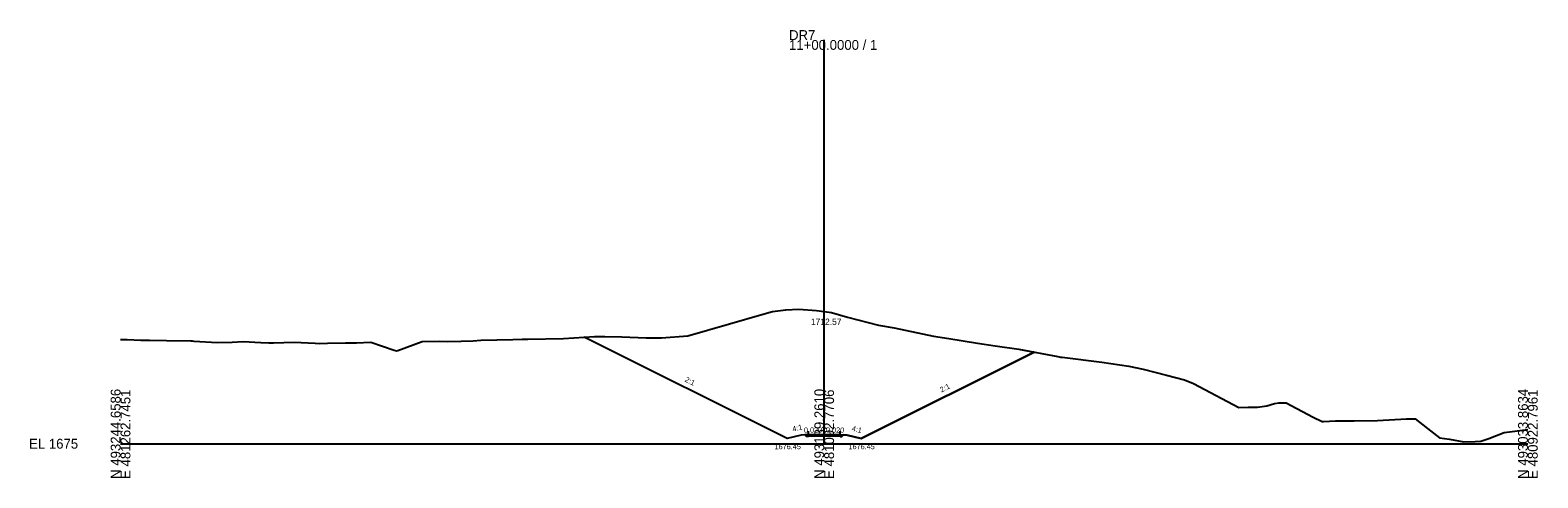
# Model space of a CAD drawing. Extents: x -26 to 403, y -10 to 4215.
# Drawn here: x -25.7 to 402.8, y 990.3 to 1117.5 of the extents above; entities that cross this region are included whole.
import ezdxf

# ---------------------------------------------------------------- set-up
doc = ezdxf.new("R2010")
doc.units = 0
for name, color, linetype in [('Exist Cross Section Cell', 7, 'Continuous'), ('Exist XS Center Line Elevation Label', 7, 'Continuous'), ('Exist XS Ground Line', 7, 'Continuous'), ('Prop XS Ditch Slope Text', 7, 'Continuous'), ('Prop XS Ditch Standard Text', 7, 'Continuous'), ('Prop XS Dump Level', 7, 'Continuous'), ('Prop XS Earthwork Shape', 7, 'Continuous'), ('Prop XS EOT Tick Mark', 7, 'Continuous'), ('Prop XS Finish Grade', 7, 'Continuous'), ('Prop XS Finish Grade Earthwork', 7, 'Continuous'), ('Prop XS Finish Grade Pavement', 7, 'Continuous'), ('Prop XS Hydro Typical Ditch Data', 7, 'Continuous'), ('Prop XS Pvmt Edge Slope', 7, 'Continuous'), ('Prop XS SE Text', 7, 'Continuous'), ('Prop XS Shoulder Borrow Shape', 7, 'Continuous'), ('Prop XS Side Slope Text', 7, 'Continuous'), ('Prop XS Subgrade Earthwork', 7, 'Continuous')]:
    doc.layers.add(name, color=color, linetype=linetype)

msp = doc.modelspace()

# ---------------------------------------------------------------- linework, layer by layer
at = {"layer": 'Exist Cross Section Cell'}
for p, q in [((200, 1000), (200, 1114.74)), ((0, 1000), (200, 1000)), ((200, 1000), (400, 1000))]:
    msp.add_line(p, q, dxfattribs=at)
at = {"layer": 'Exist XS Ground Line'}
msp.add_lwpolyline([(0, 1029.58), (1.89, 1029.58), (5.79, 1029.48), (8.21, 1029.43), (13.06, 1029.3), (19.98, 1029.23), (20.32, 1029.23), (20.86, 1029.19), (27.58, 1028.81), (31.75, 1028.9), (34.85, 1029.1), (39.84, 1028.79), (42.11, 1028.67), (43.52, 1028.72), (49.38, 1028.88), (55.29, 1028.57), (56.64, 1028.53), (58.82, 1028.59), (63.91, 1028.72), (67.06, 1028.7), (71.17, 1028.88), (77.8, 1026.57), (78.43, 1026.44), (78.83, 1026.48), (85.7, 1029.08), (90.59, 1029.13), (92.96, 1029.02), (96.78, 1029.18), (100.23, 1029.25), (102.36, 1029.42), (111.47, 1029.59), (114.13, 1029.69), (115.76, 1029.72), (125.9, 1029.94), (134.74, 1030.49), (137.67, 1030.47), (142.45, 1030.38), (149.44, 1030.06), (153.72, 1030.13), (161.21, 1030.71), (173.08, 1034.03), (182.29, 1036.73), (185.3, 1037.55), (189.12, 1038.09), (192.82, 1038.25), (197.83, 1037.89), (200, 1037.57), (202.1, 1037.26), (206.59, 1035.98), (215.42, 1033.74), (219.93, 1032.9), (231.09, 1030.53), (235.38, 1029.92), (243.59, 1028.6), (248.62, 1027.83), (255.36, 1026.85), (266.36, 1024.77), (267.13, 1024.64), (267.6, 1024.59), (278.89, 1023.14), (286.58, 1022.07), (290.66, 1021.2), (297.33, 1019.44), (302.43, 1018.14), (305.01, 1017.09), (317.87, 1010.31), (320.54, 1010.39), (323.12, 1010.36), (325.83, 1010.81), (327.98, 1011.39), (329.23, 1011.64), (331.3, 1011.66), (338.97, 1007.54), (341.53, 1006.3), (341.95, 1006.35), (345.35, 1006.51), (350.64, 1006.51), (357.22, 1006.6), (365.48, 1007.05), (368, 1007.1), (371.48, 1004.36), (374.9, 1001.72), (377.71, 1001.28), (381.84, 1000.55), (385.03, 1000.62), (386.63, 1000.74), (388.91, 1001.51), (393.28, 1003.15), (400, 1004.09)], dxfattribs=at)
at = {"layer": 'Prop XS Dump Level'}
for p, q in [((195.5, 1002.61), (200, 1002.7)), ((200, 1002.7), (204.5, 1002.61))]:
    msp.add_line(p, q, dxfattribs=at)
at = {"layer": 'Prop XS Earthwork Shape'}
msp.add_lwpolyline([(204.5, 1002.07), (200, 1002.16), (195.5, 1002.07), (194.95, 1002.05), (194.48, 1002.52), (193.5, 1002.45), (189.5, 1001.45), (131.78, 1030.3), (134.74, 1030.49), (137.67, 1030.47), (142.45, 1030.38), (149.44, 1030.06), (153.72, 1030.13), (161.21, 1030.71), (173.08, 1034.03), (182.29, 1036.73), (185.3, 1037.55), (189.12, 1038.09), (192.82, 1038.25), (197.83, 1037.89), (200, 1037.57), (202.1, 1037.26), (206.59, 1035.98), (215.42, 1033.74), (219.93, 1032.9), (231.09, 1030.53), (235.38, 1029.92), (243.59, 1028.6), (248.62, 1027.83), (255.36, 1026.85), (259.68, 1026.03), (210.5, 1001.45), (206.5, 1002.45), (205.52, 1002.52), (205.05, 1002.05)], close=True, dxfattribs=at)
at = {"layer": 'Prop XS EOT Tick Mark'}
for p, q in [((195.5, 1002.61), (195.5, 1003.61)), ((204.5, 1002.61), (204.5, 1003.61))]:
    msp.add_line(p, q, dxfattribs=at)
at = {"layer": 'Prop XS Finish Grade'}
for p, q in [((195.5, 1002.61), (194.48, 1002.52)), ((204.5, 1002.61), (205.52, 1002.52))]:
    msp.add_line(p, q, dxfattribs=at)
at = {"layer": 'Prop XS Finish Grade Earthwork'}
for p, q in [((189.5, 1001.45), (131.78, 1030.3)), ((210.5, 1001.45), (259.68, 1026.03)), ((193.5, 1002.45), (189.5, 1001.45)), ((194.48, 1002.52), (193.5, 1002.45)), ((205.52, 1002.52), (206.5, 1002.45)), ((206.5, 1002.45), (210.5, 1001.45))]:
    msp.add_line(p, q, dxfattribs=at)
at = {"layer": 'Prop XS Finish Grade Pavement'}
for p, q in [((195.5, 1002.61), (200, 1002.7)), ((200, 1002.7), (204.5, 1002.61))]:
    msp.add_line(p, q, dxfattribs=at)
at = {"layer": 'Prop XS Hydro Typical Ditch Data'}
for p, q in [((189.5, 1001.45), (131.78, 1030.3)), ((210.5, 1001.45), (259.68, 1026.03)), ((193.5, 1002.45), (189.5, 1001.45)), ((206.5, 1002.45), (210.5, 1001.45))]:
    msp.add_line(p, q, dxfattribs=at)
at = {"layer": 'Prop XS Pvmt Edge Slope'}
for p, q in [((195.5, 1002.61), (194.95, 1002.05)), ((204.5, 1002.61), (205.05, 1002.05))]:
    msp.add_line(p, q, dxfattribs=at)
at = {"layer": 'Prop XS Shoulder Borrow Shape'}
for points in [[(195.5, 1002.61), (194.48, 1002.52), (194.95, 1002.05)], [(195.5, 1002.61), (194.48, 1002.52), (194.95, 1002.05)], [(204.5, 1002.61), (205.52, 1002.52), (205.05, 1002.05)], [(204.5, 1002.61), (205.52, 1002.52), (205.05, 1002.05)]]:
    msp.add_lwpolyline(points, close=True, dxfattribs=at)
at = {"layer": 'Prop XS Subgrade Earthwork'}
for p, q in [((194.95, 1002.05), (194.48, 1002.52)), ((195.5, 1002.07), (194.95, 1002.05)), ((200, 1002.16), (195.5, 1002.07)), ((204.5, 1002.07), (200, 1002.16)), ((204.5, 1002.07), (205.05, 1002.05)), ((205.05, 1002.05), (205.52, 1002.52))]:
    msp.add_line(p, q, dxfattribs=at)

# ---------------------------------------------------------------- texts
at = {"layer": 'Exist Cross Section Cell'}
for s, p in [('11+00.0000 / 1', (190, 1111.94)), ('DR7', (190, 1114.74)), ('EL 1675', (-26, 998.6))]:
    msp.add_text(s, height=2.8, dxfattribs=at).set_placement(p)
for s, p in [('N 493244.6586', (0, 990)), ('E 481262.7451', (2.8, 990)), ('N 493139.2610', (200, 990)), ('E 481092.7706', (202.8, 990)), ('N 493033.8634', (400, 990)), ('E 480922.7961', (402.8, 990))]:
    msp.add_text(s, height=2.8, rotation=90, dxfattribs=at).set_placement(p)
at = {"layer": 'Exist XS Center Line Elevation Label'}
msp.add_text('1712.57', height=1.8, dxfattribs=at).set_placement((196.22, 1033.77))
at = {"layer": 'Prop XS Ditch Slope Text'}
for rotation, p in [(14.0362, (191.14, 1003.4)), (345.9638, (207.71, 1003.69))]:
    msp.add_text('4:1', height=1.5, rotation=rotation, dxfattribs=at).set_placement(p)
at = {"layer": 'Prop XS Ditch Standard Text'}
for p in [(185.89, 998.45), (206.89, 998.45)]:
    msp.add_text('1676.45', height=1.5, dxfattribs=at).set_placement(p)
at = {"layer": 'Prop XS Dump Level'}
for p in [(193.5, 1002.41), (206.5, 1002.41)]:
    msp.add_text('Case1', height=0.04, dxfattribs=at).set_placement(p)
at = {"layer": 'Prop XS SE Text'}
for rotation, p in [(1.1458, (194.26, 1003.1)), (358.8542, (200.49, 1003.2))]:
    msp.add_text('0.020', height=1.5, rotation=rotation, dxfattribs=at).set_placement(p)
at = {"layer": 'Prop XS Side Slope Text'}
for rotation, p in [(333.4349, (160.25, 1017.75)), (26.5651, (233.35, 1014.55))]:
    msp.add_text('2:1', height=1.5, rotation=rotation, dxfattribs=at).set_placement(p)

doc.saveas('drawing.dxf')
